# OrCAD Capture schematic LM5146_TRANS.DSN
size E; title: LM5146 5.5-V to 100-V Synchronous Buck Controller; rev: 1.0; note: Datasheet: SNVSB32     EVM: SNVU591; note: Synchronous Step Down Converter
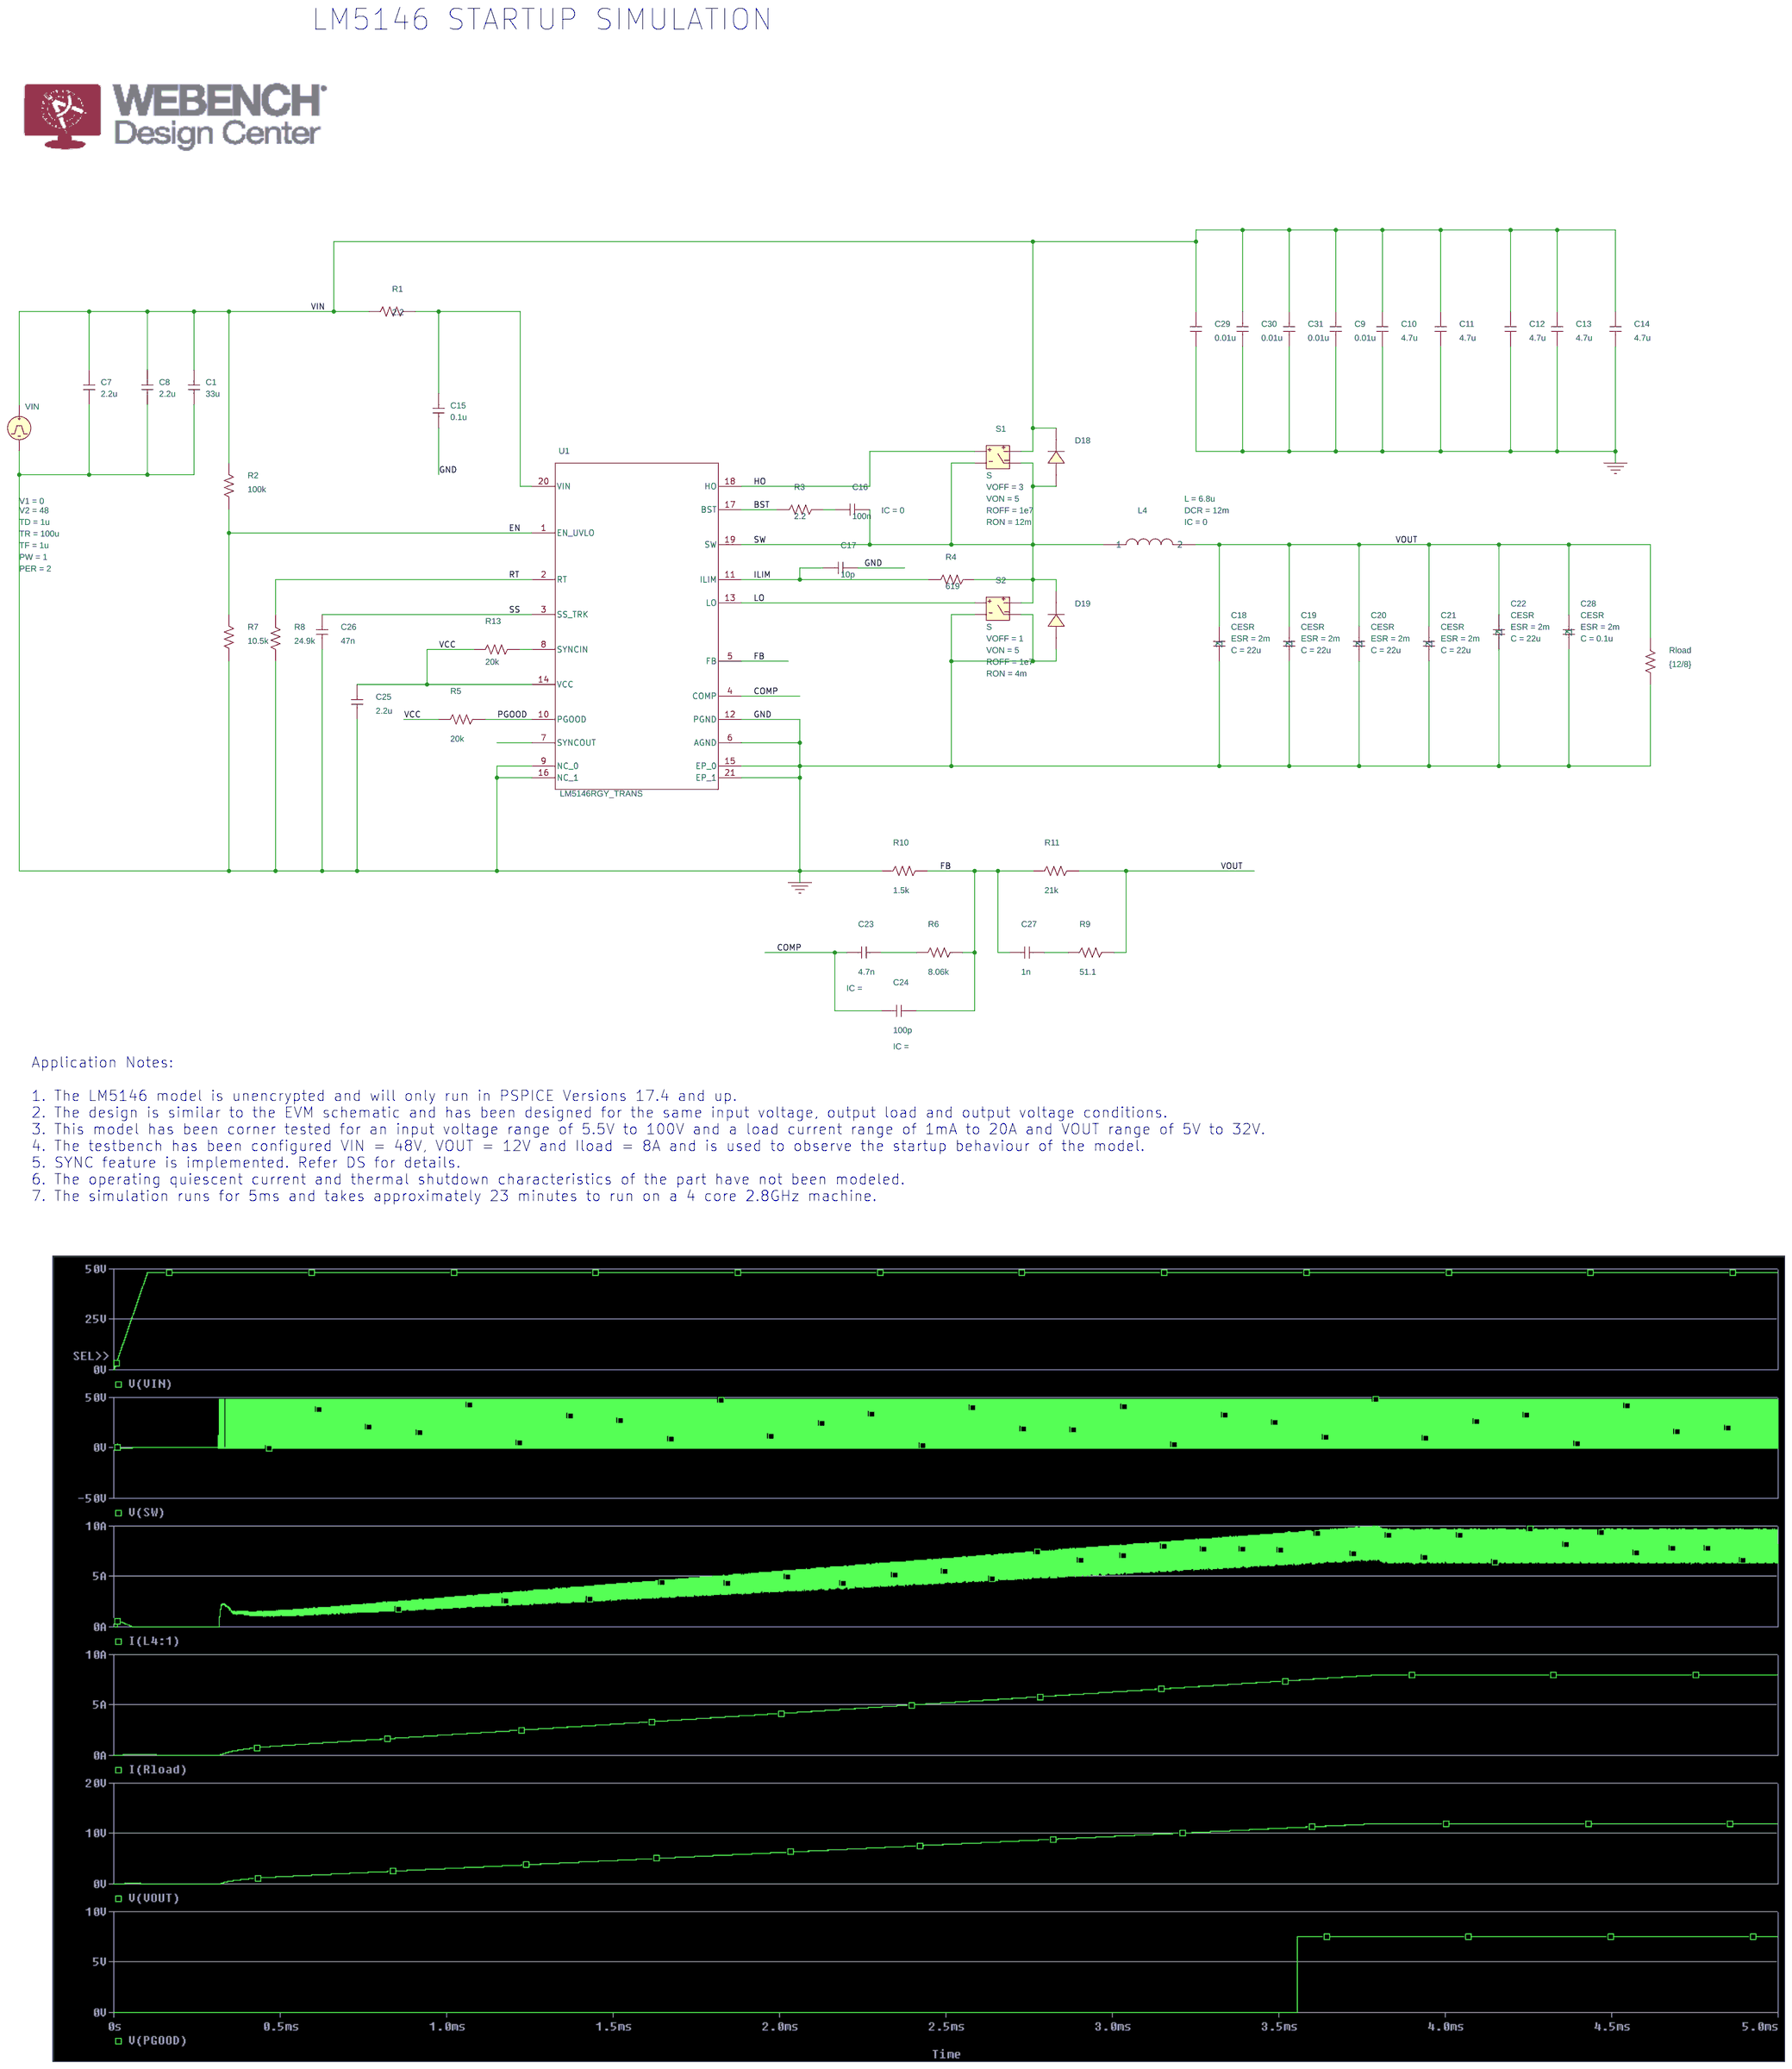
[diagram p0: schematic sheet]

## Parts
C1  33u  [RAD/CK05]
C7  2.2u  [RAD/CK05]
C8  2.2u  [RAD/CK05]
C9  0.01u  [RAD/CK05]
C10  4.7u  [RAD/CK05]
C11  4.7u  [RAD/CK05]
C12  4.7u  [RAD/CK05]
C13  4.7u  [RAD/CK05]
C14  4.7u  [RAD/CK05]
C15  0.1u  [RAD/CK05]
C16  100n  [RAD/CK05]
C17  10p  [RAD/CK05]
C18  CESR
C19  CESR
C20  CESR
C21  CESR
C22  CESR
C23  4.7n  [RAD/CK05]
C24  100p  [RAD/CK05]
C25  2.2u  [RAD/CK05]
C26  47n  [RAD/CK05]
C27  1n  [RAD/CK05]
C28  CESR
C29  0.01u  [RAD/CK05]
C30  0.01u  [RAD/CK05]
C31  0.01u  [RAD/CK05]
D18  D_D1
D19  D_D1
L4  LDCR
R1  2.2  [AX/RC05]
R2  100k  [AX/RC05]
R3  2.2  [AX/RC05]
R4  619  [AX/RC05]
R5  20k  [AX/RC05]
R6  8.06k  [AX/RC05]
R7  10.5k  [AX/RC05]
R8  24.9k  [AX/RC05]
R9  51.1  [AX/RC05]
R10  1.5k  [AX/RC05]
R11  21k  [AX/RC05]
R13  20k  [AX/RC05]
Rload  {12/8}  [AX/RC05]
S1  S
S2  S
U1  LM5146RGY_TRANS  [RGY0020B-MFG]
VIN  VPULSE

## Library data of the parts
C1 C7-C15 C17 C23-C27 C29-C31 = c
C16 = c: IC: 0
C18 = CESR_5: C: 22u; ESR: 2m; PSpiceTemplate: X^@REFDES %1 %2 @MODEL PARAMS: ?C|C=@C||C=10U| ?ESR|ESR=@ESR||ESR=2M| ?IC|IC=@IC||IC=1N| ?X|X=@X||X=1|; X: 1
C19 = CESR: C: 22u; ESR: 2m; PSpiceTemplate: X^@REFDES %1 %2 @MODEL PARAMS: ?C|C=@C||C=10U| ?ESR|ESR=@ESR||ESR=2M| ?IC|IC=@IC||IC=1N| ?X|X=@X||X=1|; X: 1
C20 = CESR_1: C: 22u; ESR: 2m; PSpiceTemplate: X^@REFDES %1 %2 @MODEL PARAMS: ?C|C=@C||C=10U| ?ESR|ESR=@ESR||ESR=2M| ?IC|IC=@IC||IC=1N| ?X|X=@X||X=1|; X: 1
C21 = CESR_4: C: 22u; ESR: 2m; PSpiceTemplate: X^@REFDES %1 %2 @MODEL PARAMS: ?C|C=@C||C=10U| ?ESR|ESR=@ESR||ESR=2M| ?IC|IC=@IC||IC=1N| ?X|X=@X||X=1|; X: 1
C22 = CESR_2: C: 22u; ESR: 2m; PSpiceTemplate: X^@REFDES %1 %2 @MODEL PARAMS: ?C|C=@C||C=10U| ?ESR|ESR=@ESR||ESR=2M| ?IC|IC=@IC||IC=1N| ?X|X=@X||X=1|; X: 1
C28 = CESR_3: C: 0.1u; ESR: 2m; PSpiceTemplate: X^@REFDES %1 %2 @MODEL PARAMS: ?C|C=@C||C=10U| ?ESR|ESR=@ESR||ESR=2M| ?IC|IC=@IC||IC=1N| ?X|X=@X||X=1|; X: 1
D18 D19 = D_D1
L4 = LDCR: DCR: 12m; IC: 0; L: 6.8u
R1 R3-R6 R8-R11 R13 = r
R2 R7 Rload = R
S1 = S: ROFF: 1e7; RON: 12m; VOFF: 3; VON: 5
S2 = S: ROFF: 1e7; RON: 4m; VOFF: 1; VON: 5
U1 = LM5146RGY_TRANS
VIN = VPULSE: PER: 2; PW: 1; TD: 1u; TF: 1u; TR: 100u; V1: 0; V2: 48

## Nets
VCC: C25.1 R5.2 R13.2 U1.14(VCC)
VIN: C1.1 C7.1 C8.1 C9.1 C10.1 C11.1 C12.1 C13.1 C14.1 C29.1 C30.1 C31.1 D18.1(C) R1.2 R2.2 S1.2(3) VIN.1(+)
0: C1.2 C7.2 C8.2 C9.2 C10.2 C11.2 C12.2 C13.2 C14.2 C15.2 C17.2 C18.2 C19.2 C20.2 C21.2 C22.2 C25.2 C26.2 C28.2 C29.2 C30.2 C31.2 D19.2(A) R7.1 R8.2 R10.2 Rload.2 S2.1(2) S2.3(4) U1.6(AGND) U1.9(NC_0) U1.12(PGND) U1.15(EP_0) U1.16(NC_1) U1.21(EP_1) VIN.2(-)
BST: R3.1 U1.17(BST)
COMP: C23.2 C24.2 U1.4(COMP)
EN: R2.1 R7.2 U1.1(EN_UVLO)
FB: C24.1 C27.2 R6.1 R10.1 R11.2 U1.5(FB)
HO: S1.0(1) U1.18(HO)
ILIM: C17.1 R4.1 U1.11(ILIM)
LO: S2.0(1) U1.13(LO)
PGOOD: R5.1 U1.10(PGOOD)
RT: R8.1 U1.2(RT)
SS: C26.1 U1.3(SS_TRK)
SW: C16.2 D18.2(A) D19.1(C) L4.1 R4.2 S1.1(2) S1.3(4) S2.2(3) U1.19(SW)
VOUT: C18.1 C19.1 C20.1 C21.1 C22.1 C28.1 L4.2 R9.1 R11.1 Rload.1
N16860193: R13.1 U1.8(SYNCIN)
N16860582: C23.1 R6.2
N16860591: C27.1 R9.2
N16860689: C15.1 R1.1 U1.20(VIN)
N16860915: C16.1 R3.2

Not connected (* = marked no-connect by the designer): U1 7(SYNCOUT)

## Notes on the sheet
- LM5146 STARTUP SIMULATION
- Application Notes:
  1. The LM5146 model is unencrypted and will only run in PSPICE Versions 17.4 and up.
  2. The design is similar to the EVM schematic and has been designed for the same input voltage, output load and output voltage conditions.
  3. This model has been corner tested for an input voltage range of 5.5V to 100V and a load current range of 1mA to 20A and VOUT range of 5V to 32V.
  4. The testbench has been configured VIN = 48V, VOUT = 12V and Iload = 8A and is used to observe the startup behaviour of the model.
  5. SYNC feature is implemented. Refer DS for details.
  6. The operating quiescent current and thermal shutdown characteristics of the part have not been modeled.
  7. The simulation runs for 5ms and takes approximately 23 minutes to run on a 4 core 2.8GHz machine.
